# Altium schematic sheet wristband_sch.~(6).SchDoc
size A2
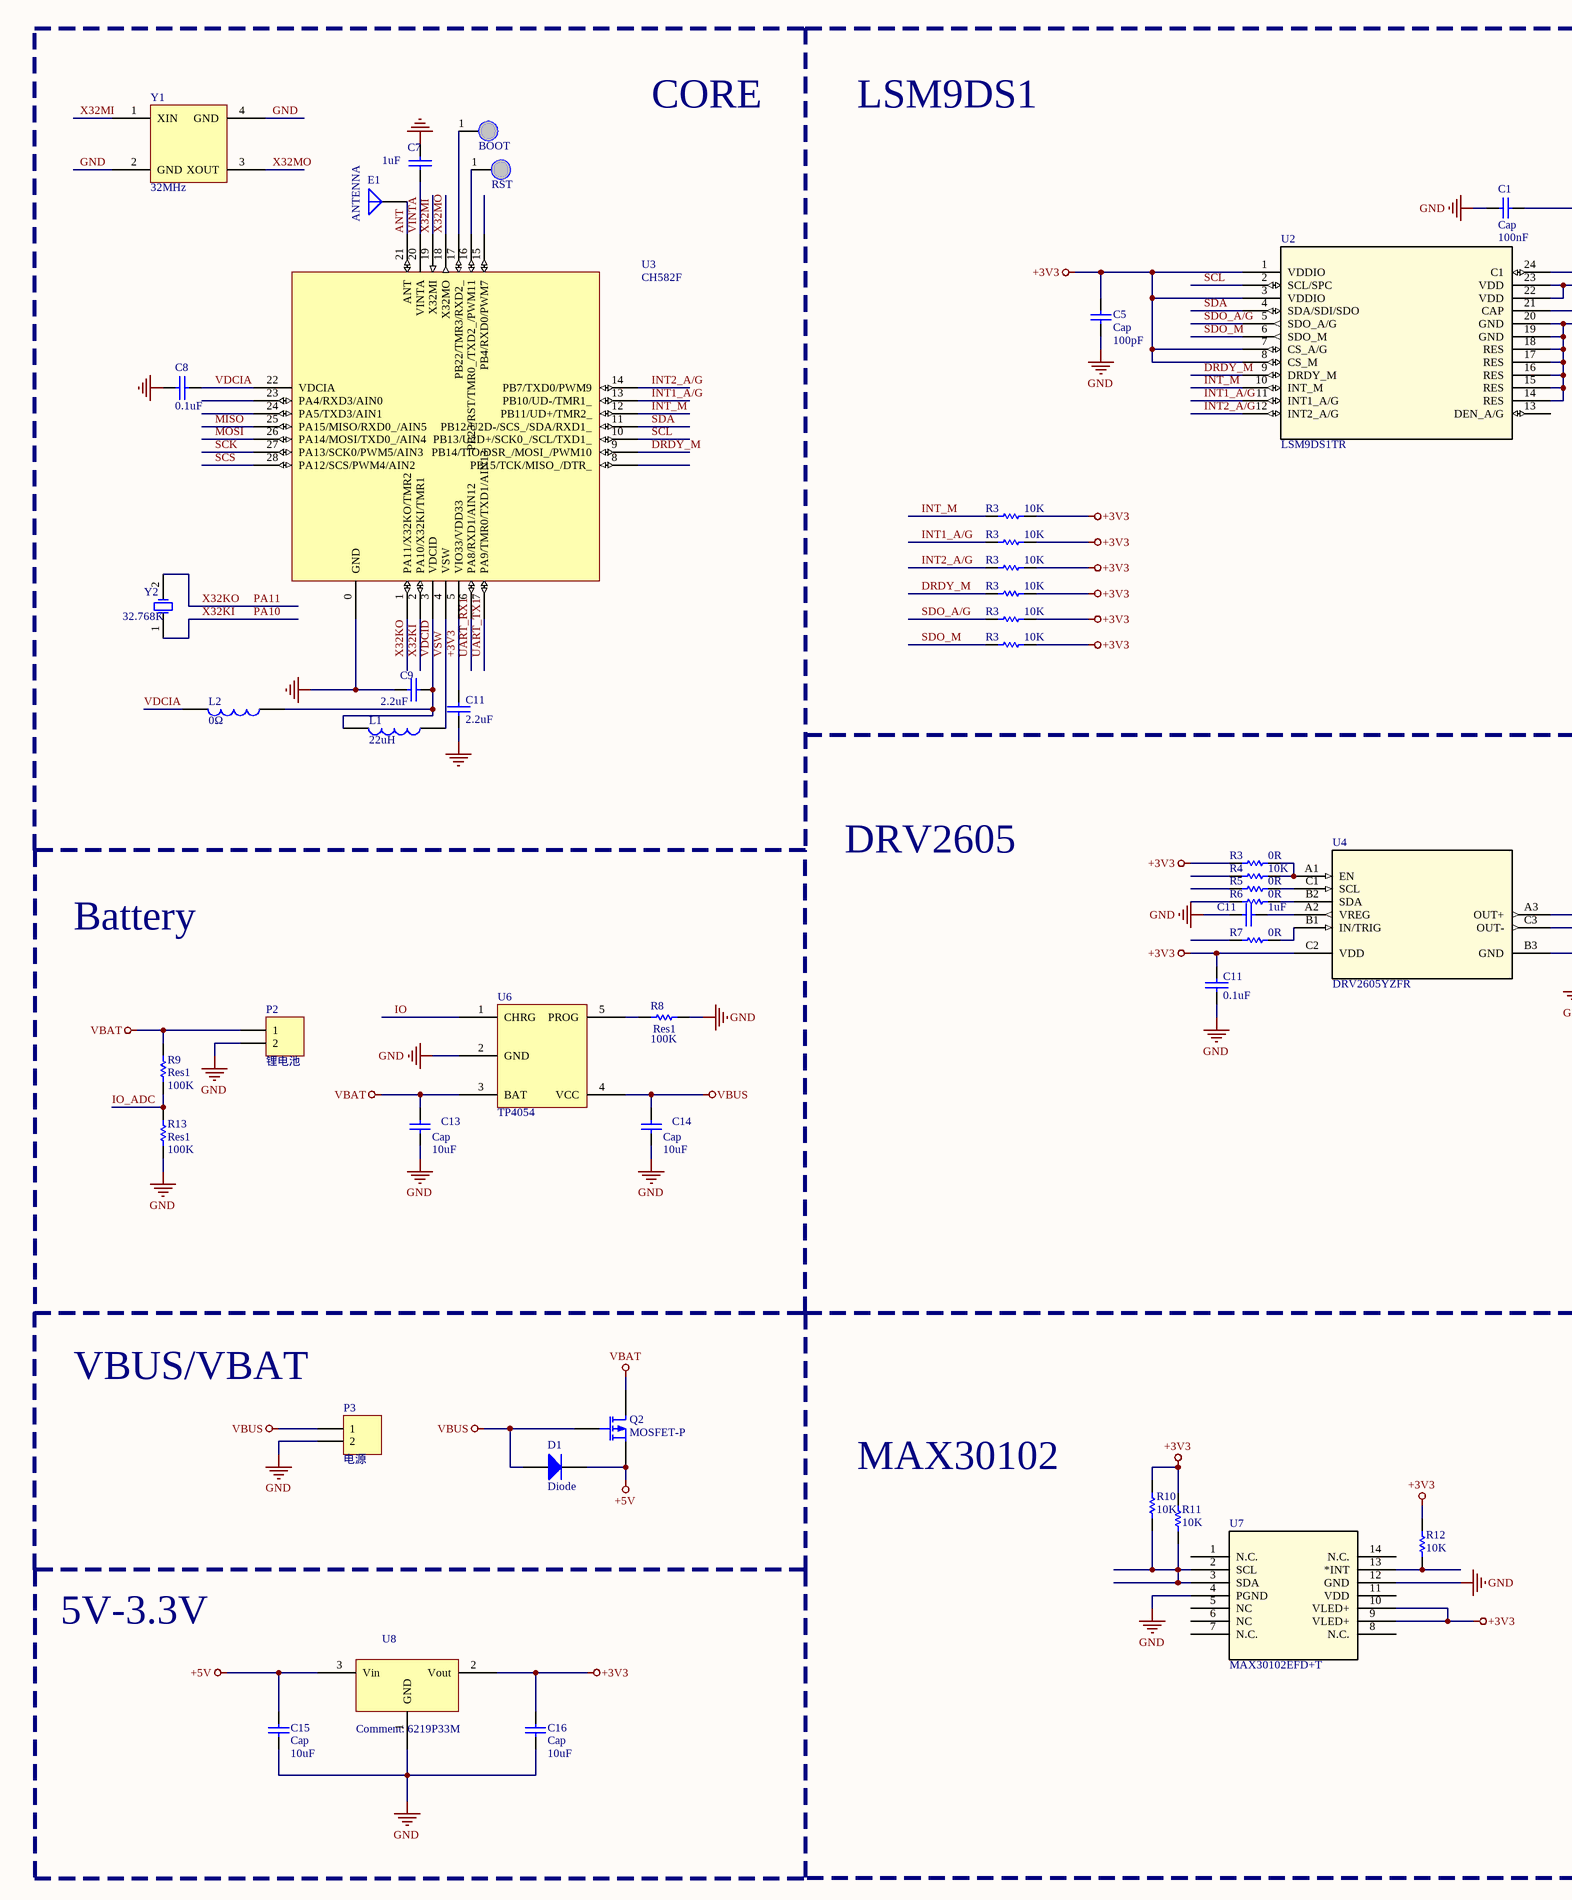
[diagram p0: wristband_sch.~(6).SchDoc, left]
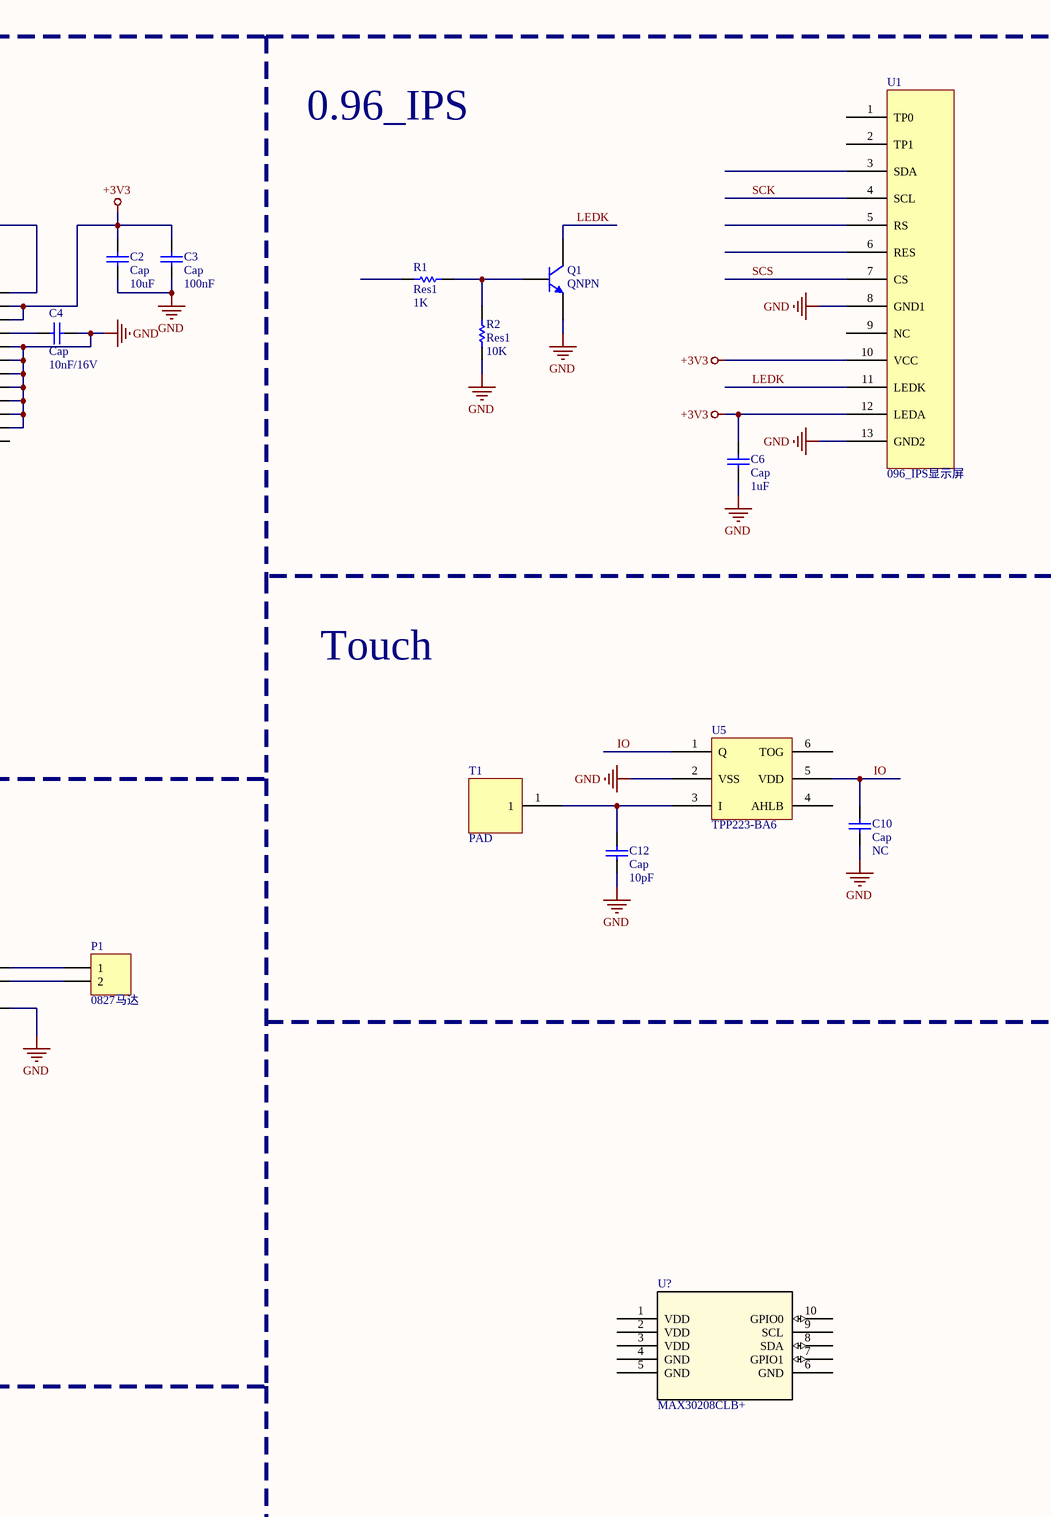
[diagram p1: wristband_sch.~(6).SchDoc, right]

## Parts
(Parts that share a designator on the sheet are numbered #1, #2 ... from top to bottom, then left to right.)
BOOT  BOOT  [TESTPOINT1]  (value not drawn)
C1  Cap  value 100nF  [RAD-0.3]
C2  Cap  value 10uF  [RAD-0.3]
C3  Cap  value 100nF  [RAD-0.3]
C4  Cap  value 10nF/16V  [RAD-0.3]
C5  Cap  value 100pF  [RAD-0.3]
C6  Cap  value 1uF  [RAD-0.3]
C7  1uF  [0402]
C8  0.1uF  [0402]
C9  2.2uF  [0402]
C10  Cap  value NC  [RAD-0.3]
C11#1  2.2uF  [0402]
C11#2  1uF  [0402]
C11#3  0.1uF  [0402]
C12  Cap  value 10pF  [RAD-0.3]
C13  Cap  value 10uF  [RAD-0.3]
C14  Cap  value 10uF  [RAD-0.3]
C15  Cap  value 10uF  [RAD-0.3]
C16  Cap  value 10uF  [RAD-0.3]
D1  Diode  [SMC]
E1  ANTENNA  [ANT-F-1-2.4G-1.6]
L1  22uH  [L2.2]
L2  0Ω  [0603]
P1  0827马达  [HDR1X2H]
P2  锂电池  [HDR1X2]
P3  电源  [HDR1X2]
Q1  QNPN  [SOT-23B_N]
Q2  MOSFET-P  [E3]
R1  Res1  value 1K  [AXIAL-0.3]
R2  Res1  value 10K  [AXIAL-0.3]
R3#1  value 10K  [AXIAL-0.3]  (hidden comment: Res1)
R3#2  value 10K  [AXIAL-0.3]  (hidden comment: Res1)
R3#3  value 10K  [AXIAL-0.3]  (hidden comment: Res1)
R3#4  value 10K  [AXIAL-0.3]  (hidden comment: Res1)
R3#5  value 10K  [AXIAL-0.3]  (hidden comment: Res1)
R3#6  value 10K  [AXIAL-0.3]  (hidden comment: Res1)
R3#7  value 0R  [AXIAL-0.3]  (hidden comment: Res1)
R4  value 10K  [AXIAL-0.3]  (hidden comment: Res1)
R5  value 0R  [AXIAL-0.3]  (hidden comment: Res1)
R6  value 0R  [AXIAL-0.3]  (hidden comment: Res1)
R7  value 0R  [AXIAL-0.3]  (hidden comment: Res1)
R8  Res1  value 100K  [AXIAL-0.3]
R9  Res1  value 100K  [AXIAL-0.3]
R10  value 10K  [AXIAL-0.3]  (hidden comment: Res1)
R11  value 10K  [AXIAL-0.3]  (hidden comment: Res1)
R12  value 10K  [AXIAL-0.3]  (hidden comment: Res1)
R13  Res1  value 100K  [AXIAL-0.3]
RST  BOOT  [TESTPOINT1]  (value not drawn)
T1  PAD
U1  096_IPS显示屏
U2  LSM9DS1TR  [LGA-24_3X3P5X1_STM]
U3  CH582F  [QFN28_4X4]
U4  DRV2605YZFR  [YZF9]
U5  TPP223-BA6
U6  TP4054
U7  MAX30102EFD+T  [21-1048_F143A5+1_MXM]
U8  6219P33M  [SOT-23]
U?  MAX30208CLB+  [21-100265_MXM]
Y1  32MHz  [3225]
Y2  32.768K  [fc-135]

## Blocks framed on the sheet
CORE: BOOT C7-C9 C11#1 E1 L1 L2 RST U3 Y1 Y2

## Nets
+3V3: C2.2 C3.2 C5.1 C6.1 C11#1.2 C11#3.2 C16.1 R3#1.2 R3#2.2 R3#3.2 R3#4.2 R3#5.2 R3#6.2 R3#7.1 R10.2 R11.2 R12.2 U1.10(VCC) U1.12(LEDA) U2.1(VDDIO) U2.3(VDDIO) U2.7(CS_A/G) U2.8(CS_M) U2.22(VDD) U2.23(VDD) U3.5(VIO33/VDD33) U4.C2(VDD) U7.9(VLED+) U7.10(VLED+) U8.2(Vout)
+5V: C15.1 D1.2(K) Q2.3(S) U8.3(Vin)
GND: C1.1 C2.1 C3.1 C4.2 C5.2 C6.2 C7.2 C8.2 C9.1 C10.2 C11#1.1 C11#2.1 C11#3.1 C12.2 C13.1 C14.1 C15.2 C16.2 P2.2 P3.2 Q1.3(E) R2.2 R8.2 R13.1 U1.8(GND1) U1.13(GND2) U2.14(RES) U2.15(RES) U2.16(RES) U2.17(RES) U2.18(RES) U2.19(GND) U2.20(GND) U3.0(GND) U4.B3(GND) U5.2(VSS) U6.2(GND) U7.4(PGND) U7.12(GND) U8.1(GND) Y1.2(GND) Y1.4(GND)
VBAT: C13.2 P2.1 Q2.1(D) R9.1 U6.3(BAT)
VBUS: C14.2 D1.1(A) P3.1 Q2.2(G) U6.4(VCC)
ANT: E1.1(A) U3.21(ANT)
DRDY_M: R3#4.1 U2.9(DRDY_M) U3.9(PB14/TIO/DSR_/MOSI_/PWM10)
INT1_A/G: R3#2.1 U2.11(INT1_A/G) U3.13(PB10/UD-/TMR1_)
INT2_A/G: R3#3.1 U2.12(INT2_A/G) U3.14(PB7/TXD0/PWM9)
INT_M: R3#1.1 U2.10(INT_M) U3.12(PB11/UD+/TMR2_)
IO: C10.1 U5.1(Q) U5.5(VDD) U6.1(CHRG)
IO_ADC: R9.2 R13.2
LEDK: Q1.1(C) U1.11(LEDK)
MISO: U3.25(PA15/MISO/RXD0_/AIN5)
MOSI: U3.26(PA14/MOSI/TXD0_/AIN4)
PA10: U3.2(PA10/X32KI/TMR1) Y2.1(OSC1)  [also labelled X32KI]
PA11: U3.1(PA11/X32KO/TMR2) Y2.2(OSC2)  [also labelled X32KO]
SCK: U1.4(SCL) U3.27(PA13/SCK0/PWM5/AIN3)
SCL: U2.2(SCL/SPC) U3.10(PB13/U2D+/SCK0_/SCL/TXD1_)
SCS: U1.7(CS) U3.28(PA12/SCS/PWM4/AIN2)
SDA: U2.4(SDA/SDI/SDO) U3.11(PB12/U2D-/SCS_/SDA/RXD1_)
SDO_A/G: R3#5.1 U2.5(SDO_A/G)
SDO_M: R3#6.1 U2.6(SDO_M)
UART_RX1: U3.6(PA8/RXD1/AIN12)
UART_TX1: U3.7(PA9/TMR0/TXD1/AIN13)
VDCIA: C8.1 L2.2 U3.22(VDCIA)
VDCID: C9.2 L1.2 L2.1 U3.3(VDCID)
VINTA: C7.1 U3.20(VINTA)
VSW: L1.1 U3.4(VSW)
X32MI: U3.19(X32MI) Y1.1(XIN)
X32MO: U3.18(X32MO) Y1.3(XOUT)
NetBOOT_1: BOOT.1 U3.17(PB22/TMR3/RXD2_)
NetC1_2: C1.2 U2.24(C1)
NetC4_1: C4.1 U2.21(CAP)
NetC11#2_2: C11#2.2 U4.A2(VREG)
NetC12_1: C12.1 T1.1 U5.3(I)
NetP1_1: P1.1 U4.A3(OUT+)
NetP1_2: P1.2 U4.C3(OUT-)
NetQ1_2: Q1.2(B) R1.1 R2.1
NetR3#7_2: R3#7.2 R4.2 U4.A1(EN)
NetR5_2: R5.2 U4.C1(SCL)
NetR6_2: R6.2 U4.B2(SDA)
NetR7_2: R7.2 U4.B1(IN/TRIG)
NetR8_1: R8.1 U6.5(PROG)
NetR10_1: R10.1 R11.1 U7.2(SCL) U7.3(SDA)
NetR12_1: R12.1 U7.13(*INT)
NetRST_1: RST.1 U3.16(PB23/RST/TMR0_/TXD2_/PWM11)

Not connected (* = marked no-connect by the designer): R1 2; R4 1; R5 1; R6 1; R7 1; U1 1(TP0) 2(TP1) 3(SDA) 5(RS) 6(RES) 9(NC); U2 13(DEN_A/G); U3 8(PB15/TCK/MISO_/DTR_) 15(PB4/RXD0/PWM7) 23(PA4/RXD3/AIN0) 24(PA5/TXD3/AIN1); U5 4(AHLB) 6(TOG); U7 1(N.C.) 5(NC) 6(NC) 7(N.C.) 8(N.C.) 11(VDD) 14(N.C.); U? 1(VDD) 2(VDD) 3(VDD) 4(GND) 5(GND) 6(GND) 7(GPIO1) 8(SDA) 9(SCL) 10(GPIO0)

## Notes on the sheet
- LSM9DS1
- 0.96_IPS
- Touch
- DRV2605
- Battery
- VBUS/VBAT
- MAX30102
- 5V-3.3V

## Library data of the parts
BOOT RST = PAD 1.2MM
C1-C6 C10 C12-C16 = Cap: Capacitor
C7-C9 C11#1-C11#3 = CAP: Capacitor
D1 = Diode: Default Diode
E1 = ANTENNA: Generic Antenna
L1 L2 = INDUCTOR
P1 = Header 2H: Header, 2-Pin, Right Angle
P2 P3 = Header 2: Header, 2-Pin
Q1 = QNPN: NPN Bipolar Transistor
Q2 = MOSFET-P: P-Channel MOSFET
R1 R2 R3#1-R3#7 R4-R13 = Res1: Resistor
U1 = Component_1
U2 = LSM9DS1TR: No Description Available; Vendor: STMicroelectronics; Built_By: EMA_Jessica; SourceLibrary: Updates_to_database_2020-11-03
U3 = CH582F: RISC-V MCU with BLE/2*USB/ADC/PWM/SPI/I2C/4*UART
U4 = DRV2605YZFR: No Description Available; Vendor: TEXAS INSTRUMENTS
U7 = MAX30102EFD+T: No Description Available; SourceLibrary: Update_to_database_2021-01-29; Built_By: EMA_UL_Team; Vendor: Maxim Integrated Products
U? = MAX30208CLB+: No Description Available; Vendor: Maxim Integrated Products; Built_By: EMA_Rebekah; SourceLibrary: Maxim_2019-09-13
Y1 = 晶体
Y2 = XTAL: Crystal Oscillator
